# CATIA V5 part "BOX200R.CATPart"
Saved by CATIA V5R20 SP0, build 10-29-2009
Part number: BOX200R
Bounding box of the stored display mesh (mm): x 0 to 320, y -20 to 55, z -41.5 to 15
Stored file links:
  C:\Users\Utente\Desktop\IO LAVORO\3D X SITO CF\X SITO\PLASTICA\BOX\BOX200R.CATPart
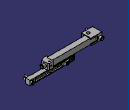
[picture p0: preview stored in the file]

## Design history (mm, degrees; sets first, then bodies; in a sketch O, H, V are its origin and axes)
Set1
  DatumSurface1 to DatumSurface16 "_ZH90/2_head"
  DatumSurface17 to DatumSurface34 "_ZH90/2_screw1"
  DatumSurface35 to DatumSurface55 "_ZH90/2_hand"
  DatumSurface56 to DatumSurface73 "_ZH90/2_screw2"
  DatumSurface74 to DatumSurface94 "_ZH90/2_he"
  DatumSurface95 to DatumSurface109 "_ZH90/2_screw3"
  DatumSurface110 to DatumSurface117 "_ZH90/2_stift1"
  DatumSurface118 to DatumSurface127 "_ZH90/2_stift2"
  DatumSurface128 to DatumSurface845 "_ZH90/02_body"
  DatumSurface846 to DatumSurface863 "_M8-5"
  DatumSurface864 to DatumSurface883 "_ST2"
  DatumSurface884 to DatumSurface929 "_ZH90/02_foot1u"
  DatumSurface930 to DatumSurface952 "_ZH90/02_foot1d"
  DatumSurface953 to DatumSurface970 "_M5-1"
  DatumSurface971 to DatumSurface993 "_ZH90/02_foot2u"
  DatumSurface994 to DatumSurface1027 "_ZH90/02_foot2d"
  DatumSurface1028 to DatumSurface1045 "_M5-2"
Body1 (main body)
